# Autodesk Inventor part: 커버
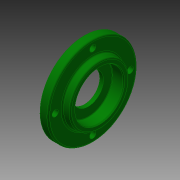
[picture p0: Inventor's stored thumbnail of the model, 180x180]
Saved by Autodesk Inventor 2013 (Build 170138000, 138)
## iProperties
Created: 2018-11
Part Number: 커버
Material: 알루미늄 6061
Document SubType Name: Modeling
Designer: mduedu
Density: 1 g/cm^3
Author: mduedu
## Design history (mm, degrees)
sketch "스케치1"
  geometry: L1 (0, 0)-(3, 0); L2 (3, 0)-(3, 23.5); L3 (3, 23.5)-(0, 23.5); L4 (0, 23.5)-(0, 0); L5 (3, 0)-(9, 0); L6 (9, 0)-(9, 32); L7 (9, 32)-(3, 32); L8 (3, 32)-(3, 0); L9 (9, 0)-(14, 0); L10 (14, 0)-(14, 21.118); L11 (9, 22)-(9, 0); L12 (9, 22)-(14, 21.118)
  constraints: 24 end point, 5 parallel, 3 horizontal, 3 perpendicular
  dimensions: "d0" = 64 diameter of L7 L5; "d3" = 47 diameter of L3 L1; "d4" = 3 distance of L2.end L3.end; "d5" = 6 distance of L6.end L7.end; "d6" = 14 distance between parallel lines of L10 L4; "d37" = 44 diameter of L11.start L9; "d38" = 10 deg angle of L9 L12
revolve "회전1" sketch "스케치1" stored, may be unused: angle "d7" = 90 deg
sketch "스케치2"
  geometry: L1 (0, -23.5)-(0, 23.5) reference; L2 (0, 23.5)-(3, 23.5) reference; L3 (3, 23.5)-(3, 32) reference; L4 (3, 32)-(9, 32) reference; L5 (9, 32)-(9, 22) reference; L6 (9, -22)-(9, -32) reference; L7 (9, -32)-(3, -32) reference; L8 (3, -32)-(3, -23.5) reference; L9 (3, -23.5)-(0, -23.5) reference; L10 (0, 0)-(3, 0); L11 (3, 0)-(3, 20); L12 (3, 20)-(0, 20); L13 (0, 20)-(0, 0); L14 (3, 0)-(5.7, 0); L15 (5.7, 0)-(5.7, 12.5); L16 (5.7, 12.5)-(3, 12.5); L17 (3, 12.5)-(3, 0); L18 (5.7, 0)-(14, 0); L19 (14, 0)-(14, 17.5); L20 (14, 17.5)-(5.7, 17.5); L21 (5.7, 17.5)-(5.7, 0); L22 (9, 22)-(14, 21.118) reference; L23 (14, 21.118)-(14, -21.118) reference; L24 (14, -21.118)-(9, -22) reference
  constraints: 24 end point, 6 parallel, 3 horizontal, 3 perpendicular, 1 midpoint
  dimensions: "d8" = 35 diameter of L20 L18; "d10" = 25 diameter of L16 L14; "d11" = 40 diameter of L12 L10; "d12" = 3 distance of L11.end L12.end; "d13" = 8.3 distance of L19.end L20.end
revolve "회전2" sketch "스케치2" stored, may be unused: angle "d14" = 90 deg
fillet "모깎기1" dims "d15" = 0.3
chamfer "모따기1" distance "d16" = 0.8; stored, may be unused: second distance "d17" = 2, angle "d18" = 30 deg
fillet "모깎기2" dims "d19" = 1, "d35" = 3
chamfer "모따기2" distance "d20" = 0.5; stored, may be unused: second distance "d21" = 2, angle "d22" = 30 deg
sketch "스케치3" dims "d23" = 52
  geometry: 6 further points
  constraints: 2 vertical alignment, 1 coincident, 7 other
  dimensions: "d26" = 360 deg dimension on point (0, 0) point (0, 26) (derived)
sketch "스케치4" dims "d39" = 54
  geometry: C1 r 32 at (0, 0) reference; 5 further points
  constraints: 2 vertical alignment, 1 coincident, 7 other
  dimensions: "d43" = 360 deg dimension on C1.centre point (0, 27) (derived)
hole "구멍1" sketch "스케치4" at (0, 27), (-27, 0), (0, -27), (27, 0) diameter "d28" = 4.5; stored, may be unused: countersink angle "d32" = 90 deg, drill point angle "d34" = 0 deg; dims "d29" = 6, "d30" = 8, "d31" = 4.6, "d33" = 8
node "솔리드1"
node "절단 모서리 투영1"
